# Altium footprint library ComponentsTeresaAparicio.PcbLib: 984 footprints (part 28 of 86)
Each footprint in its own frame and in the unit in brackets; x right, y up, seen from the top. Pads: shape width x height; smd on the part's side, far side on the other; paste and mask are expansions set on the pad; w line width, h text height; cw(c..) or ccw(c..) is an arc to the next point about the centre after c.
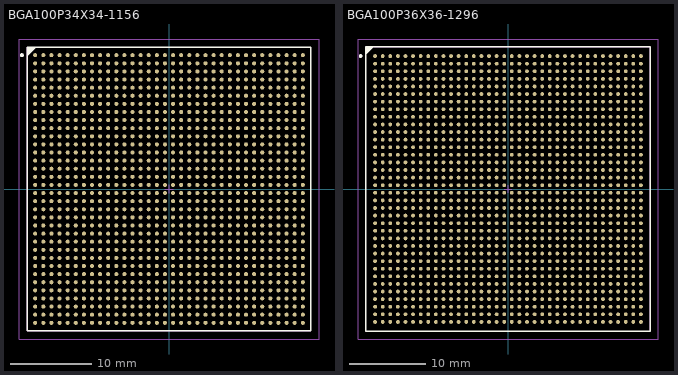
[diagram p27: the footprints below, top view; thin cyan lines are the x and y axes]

## BGA100P34X34-1156 [mm] "BGA, 1156-Leads, Body 35x35mm, Pitch 1mm"
height 3.5
pads (1156):
  round 0.5 smd: A1(-16.5,16.5) A2(-15.5,16.5) A3(-14.5,16.5) A4(-13.5,16.5) A5(-12.5,16.5) A6(-11.5,16.5) A7(-10.5,16.5) A8(-9.5,16.5) A9(-8.5,16.5) A10(-7.5,16.5) A11(-6.5,16.5) A12(-5.5,16.5) A13(-4.5,16.5) A14(-3.5,16.5) A15(-2.5,16.5) A16(-1.5,16.5) A17(-0.5,16.5) A18(0.5,16.5) A19(1.5,16.5) A20(2.5,16.5) A21(3.5,16.5) A22(4.5,16.5) A23(5.5,16.5) A24(6.5,16.5) A25(7.5,16.5) A26(8.5,16.5) A27(9.5,16.5) A28(10.5,16.5) A29(11.5,16.5) A30(12.5,16.5) A31(13.5,16.5) A32(14.5,16.5) A33(15.5,16.5) A34(16.5,16.5) AA1(-16.5,-3.5) AA2(-15.5,-3.5) AA3(-14.5,-3.5) AA4(-13.5,-3.5) AA5(-12.5,-3.5) AA6(-11.5,-3.5) AA7(-10.5,-3.5) AA8(-9.5,-3.5) AA9(-8.5,-3.5) AA10(-7.5,-3.5) AA11(-6.5,-3.5) AA12(-5.5,-3.5) AA13(-4.5,-3.5) AA14(-3.5,-3.5) AA15(-2.5,-3.5) AA16(-1.5,-3.5) AA17(-0.5,-3.5) AA18(0.5,-3.5) AA19(1.5,-3.5) AA20(2.5,-3.5) AA21(3.5,-3.5) AA22(4.5,-3.5) AA23(5.5,-3.5) AA24(6.5,-3.5) AA25(7.5,-3.5) AA26(8.5,-3.5) AA27(9.5,-3.5) AA28(10.5,-3.5) AA29(11.5,-3.5) AA30(12.5,-3.5) AA31(13.5,-3.5) AA32(14.5,-3.5) AA33(15.5,-3.5) AA34(16.5,-3.5) AB1(-16.5,-4.5) AB2(-15.5,-4.5) AB3(-14.5,-4.5) AB4(-13.5,-4.5) AB5(-12.5,-4.5) AB6(-11.5,-4.5) AB7(-10.5,-4.5) AB8(-9.5,-4.5) AB9(-8.5,-4.5) AB10(-7.5,-4.5) AB11(-6.5,-4.5) AB12(-5.5,-4.5) AB13(-4.5,-4.5) AB14(-3.5,-4.5) AB15(-2.5,-4.5) AB16(-1.5,-4.5) AB17(-0.5,-4.5) AB18(0.5,-4.5) AB19(1.5,-4.5) AB20(2.5,-4.5) AB21(3.5,-4.5) AB22(4.5,-4.5) AB23(5.5,-4.5) AB24(6.5,-4.5) AB25(7.5,-4.5) AB26(8.5,-4.5) AB27(9.5,-4.5) AB28(10.5,-4.5) AB29(11.5,-4.5) AB30(12.5,-4.5) AB31(13.5,-4.5) AB32(14.5,-4.5) AB33(15.5,-4.5) AB34(16.5,-4.5) AC1(-16.5,-5.5) AC2(-15.5,-5.5) AC3(-14.5,-5.5) AC4(-13.5,-5.5) AC5(-12.5,-5.5) AC6(-11.5,-5.5) AC7(-10.5,-5.5) AC8(-9.5,-5.5) AC9(-8.5,-5.5) AC10(-7.5,-5.5) AC11(-6.5,-5.5) AC12(-5.5,-5.5) AC13(-4.5,-5.5) AC14(-3.5,-5.5) AC15(-2.5,-5.5) AC16(-1.5,-5.5) AC17(-0.5,-5.5) AC18(0.5,-5.5) AC19(1.5,-5.5) AC20(2.5,-5.5) AC21(3.5,-5.5) AC22(4.5,-5.5) AC23(5.5,-5.5) AC24(6.5,-5.5) AC25(7.5,-5.5) AC26(8.5,-5.5) AC27(9.5,-5.5) AC28(10.5,-5.5) AC29(11.5,-5.5) AC30(12.5,-5.5) AC31(13.5,-5.5) AC32(14.5,-5.5) AC33(15.5,-5.5) AC34(16.5,-5.5) AD1(-16.5,-6.5) AD2(-15.5,-6.5) AD3(-14.5,-6.5) AD4(-13.5,-6.5) AD5(-12.5,-6.5) AD6(-11.5,-6.5) AD7(-10.5,-6.5) AD8(-9.5,-6.5) AD9(-8.5,-6.5) AD10(-7.5,-6.5) AD11(-6.5,-6.5) AD12(-5.5,-6.5) AD13(-4.5,-6.5) AD14(-3.5,-6.5) AD15(-2.5,-6.5) AD16(-1.5,-6.5) AD17(-0.5,-6.5) AD18(0.5,-6.5) AD19(1.5,-6.5) AD20(2.5,-6.5) AD21(3.5,-6.5) AD22(4.5,-6.5) AD23(5.5,-6.5) AD24(6.5,-6.5) AD25(7.5,-6.5) AD26(8.5,-6.5) AD27(9.5,-6.5) AD28(10.5,-6.5) AD29(11.5,-6.5) AD30(12.5,-6.5) AD31(13.5,-6.5) AD32(14.5,-6.5) AD33(15.5,-6.5) AD34(16.5,-6.5) AE1(-16.5,-7.5) AE2(-15.5,-7.5) AE3(-14.5,-7.5) AE4(-13.5,-7.5) AE5(-12.5,-7.5) AE6(-11.5,-7.5) AE7(-10.5,-7.5) AE8(-9.5,-7.5) AE9(-8.5,-7.5) AE10(-7.5,-7.5) AE11(-6.5,-7.5) AE12(-5.5,-7.5) AE13(-4.5,-7.5) AE14(-3.5,-7.5) AE15(-2.5,-7.5) AE16(-1.5,-7.5) AE17(-0.5,-7.5) AE18(0.5,-7.5) AE19(1.5,-7.5) AE20(2.5,-7.5) AE21(3.5,-7.5) AE22(4.5,-7.5) AE23(5.5,-7.5) AE24(6.5,-7.5) AE25(7.5,-7.5) AE26(8.5,-7.5) AE27(9.5,-7.5) AE28(10.5,-7.5) AE29(11.5,-7.5) AE30(12.5,-7.5) AE31(13.5,-7.5) AE32(14.5,-7.5) AE33(15.5,-7.5) AE34(16.5,-7.5) AF1(-16.5,-8.5) AF2(-15.5,-8.5) AF3(-14.5,-8.5) AF4(-13.5,-8.5) AF5(-12.5,-8.5) AF6(-11.5,-8.5) AF7(-10.5,-8.5) AF8(-9.5,-8.5) AF9(-8.5,-8.5) AF10(-7.5,-8.5) AF11(-6.5,-8.5) AF12(-5.5,-8.5) AF13(-4.5,-8.5) AF14(-3.5,-8.5) AF15(-2.5,-8.5) AF16(-1.5,-8.5) AF17(-0.5,-8.5) AF18(0.5,-8.5) AF19(1.5,-8.5) AF20(2.5,-8.5) AF21(3.5,-8.5) AF22(4.5,-8.5) AF23(5.5,-8.5) AF24(6.5,-8.5) AF25(7.5,-8.5) AF26(8.5,-8.5) AF27(9.5,-8.5) AF28(10.5,-8.5) AF29(11.5,-8.5) AF30(12.5,-8.5) AF31(13.5,-8.5) AF32(14.5,-8.5) AF33(15.5,-8.5) AF34(16.5,-8.5) AG1(-16.5,-9.5) AG2(-15.5,-9.5) AG3(-14.5,-9.5) AG4(-13.5,-9.5) AG5(-12.5,-9.5) AG6(-11.5,-9.5) AG7(-10.5,-9.5) AG8(-9.5,-9.5) AG9(-8.5,-9.5) AG10(-7.5,-9.5) AG11(-6.5,-9.5) AG12(-5.5,-9.5) AG13(-4.5,-9.5) AG14(-3.5,-9.5) AG15(-2.5,-9.5) AG16(-1.5,-9.5) AG17(-0.5,-9.5) AG18(0.5,-9.5) AG19(1.5,-9.5) AG20(2.5,-9.5) AG21(3.5,-9.5) AG22(4.5,-9.5) AG23(5.5,-9.5) AG24(6.5,-9.5) AG25(7.5,-9.5) AG26(8.5,-9.5) AG27(9.5,-9.5) AG28(10.5,-9.5) AG29(11.5,-9.5) AG30(12.5,-9.5) AG31(13.5,-9.5) AG32(14.5,-9.5) AG33(15.5,-9.5) AG34(16.5,-9.5) AH1(-16.5,-10.5) AH2(-15.5,-10.5) AH3(-14.5,-10.5) AH4(-13.5,-10.5) AH5(-12.5,-10.5) AH6(-11.5,-10.5) AH7(-10.5,-10.5) AH8(-9.5,-10.5) AH9(-8.5,-10.5) AH10(-7.5,-10.5) AH11(-6.5,-10.5) AH12(-5.5,-10.5) AH13(-4.5,-10.5) AH14(-3.5,-10.5) AH15(-2.5,-10.5) AH16(-1.5,-10.5) AH17(-0.5,-10.5) AH18(0.5,-10.5) AH19(1.5,-10.5) AH20(2.5,-10.5) AH21(3.5,-10.5) AH22(4.5,-10.5) AH23(5.5,-10.5) AH24(6.5,-10.5) AH25(7.5,-10.5) AH26(8.5,-10.5) AH27(9.5,-10.5) AH28(10.5,-10.5) AH29(11.5,-10.5) AH30(12.5,-10.5) AH31(13.5,-10.5) AH32(14.5,-10.5) AH33(15.5,-10.5) AH34(16.5,-10.5) AJ1(-16.5,-11.5) AJ2(-15.5,-11.5) AJ3(-14.5,-11.5) AJ4(-13.5,-11.5) AJ5(-12.5,-11.5) AJ6(-11.5,-11.5) AJ7(-10.5,-11.5) AJ8(-9.5,-11.5) AJ9(-8.5,-11.5) AJ10(-7.5,-11.5) AJ11(-6.5,-11.5) AJ12(-5.5,-11.5) AJ13(-4.5,-11.5) AJ14(-3.5,-11.5) AJ15(-2.5,-11.5) AJ16(-1.5,-11.5) AJ17(-0.5,-11.5) AJ18(0.5,-11.5) AJ19(1.5,-11.5) AJ20(2.5,-11.5) AJ21(3.5,-11.5) AJ22(4.5,-11.5) AJ23(5.5,-11.5) AJ24(6.5,-11.5) AJ25(7.5,-11.5) AJ26(8.5,-11.5) AJ27(9.5,-11.5) AJ28(10.5,-11.5) AJ29(11.5,-11.5) AJ30(12.5,-11.5) AJ31(13.5,-11.5) AJ32(14.5,-11.5) AJ33(15.5,-11.5) AJ34(16.5,-11.5) AK1(-16.5,-12.5) AK2(-15.5,-12.5) AK3(-14.5,-12.5) AK4(-13.5,-12.5) AK5(-12.5,-12.5) AK6(-11.5,-12.5) AK7(-10.5,-12.5) AK8(-9.5,-12.5) AK9(-8.5,-12.5) AK10(-7.5,-12.5) AK11(-6.5,-12.5) AK12(-5.5,-12.5) AK13(-4.5,-12.5) AK14(-3.5,-12.5) AK15(-2.5,-12.5) AK16(-1.5,-12.5) AK17(-0.5,-12.5) AK18(0.5,-12.5) AK19(1.5,-12.5) AK20(2.5,-12.5) AK21(3.5,-12.5) AK22(4.5,-12.5) AK23(5.5,-12.5) AK24(6.5,-12.5) AK25(7.5,-12.5) AK26(8.5,-12.5) AK27(9.5,-12.5) AK28(10.5,-12.5) AK29(11.5,-12.5) AK30(12.5,-12.5) AK31(13.5,-12.5) AK32(14.5,-12.5) AK33(15.5,-12.5) AK34(16.5,-12.5) AL1(-16.5,-13.5) AL2(-15.5,-13.5) AL3(-14.5,-13.5) AL4(-13.5,-13.5) AL5(-12.5,-13.5) AL6(-11.5,-13.5) AL7(-10.5,-13.5) AL8(-9.5,-13.5) AL9(-8.5,-13.5) AL10(-7.5,-13.5) AL11(-6.5,-13.5) AL12(-5.5,-13.5) AL13(-4.5,-13.5) AL14(-3.5,-13.5) AL15(-2.5,-13.5) AL16(-1.5,-13.5) AL17(-0.5,-13.5) AL18(0.5,-13.5) AL19(1.5,-13.5) AL20(2.5,-13.5) AL21(3.5,-13.5) AL22(4.5,-13.5) AL23(5.5,-13.5) AL24(6.5,-13.5) AL25(7.5,-13.5) AL26(8.5,-13.5) AL27(9.5,-13.5) AL28(10.5,-13.5) AL29(11.5,-13.5) AL30(12.5,-13.5) AL31(13.5,-13.5) AL32(14.5,-13.5) AL33(15.5,-13.5) AL34(16.5,-13.5) AM1(-16.5,-14.5) AM2(-15.5,-14.5) AM3(-14.5,-14.5) AM4(-13.5,-14.5) AM5(-12.5,-14.5) AM6(-11.5,-14.5) AM7(-10.5,-14.5) AM8(-9.5,-14.5) AM9(-8.5,-14.5) AM10(-7.5,-14.5) AM11(-6.5,-14.5) AM12(-5.5,-14.5) AM13(-4.5,-14.5) AM14(-3.5,-14.5) AM15(-2.5,-14.5) AM16(-1.5,-14.5) AM17(-0.5,-14.5) AM18(0.5,-14.5) AM19(1.5,-14.5) AM20(2.5,-14.5) AM21(3.5,-14.5) AM22(4.5,-14.5) AM23(5.5,-14.5) AM24(6.5,-14.5) AM25(7.5,-14.5) AM26(8.5,-14.5) AM27(9.5,-14.5) AM28(10.5,-14.5) AM29(11.5,-14.5) AM30(12.5,-14.5) AM31(13.5,-14.5) AM32(14.5,-14.5) AM33(15.5,-14.5) AM34(16.5,-14.5) AN1(-16.5,-15.5) AN2(-15.5,-15.5) AN3(-14.5,-15.5) AN4(-13.5,-15.5) AN5(-12.5,-15.5) AN6(-11.5,-15.5) AN7(-10.5,-15.5) AN8(-9.5,-15.5) AN9(-8.5,-15.5) AN10(-7.5,-15.5) AN11(-6.5,-15.5) AN12(-5.5,-15.5) AN13(-4.5,-15.5) AN14(-3.5,-15.5) AN15(-2.5,-15.5) AN16(-1.5,-15.5) AN17(-0.5,-15.5) AN18(0.5,-15.5) AN19(1.5,-15.5) AN20(2.5,-15.5) AN21(3.5,-15.5) AN22(4.5,-15.5) AN23(5.5,-15.5) AN24(6.5,-15.5) AN25(7.5,-15.5) AN26(8.5,-15.5) AN27(9.5,-15.5) AN28(10.5,-15.5) AN29(11.5,-15.5) AN30(12.5,-15.5) AN31(13.5,-15.5) AN32(14.5,-15.5) AN33(15.5,-15.5) AN34(16.5,-15.5) AP1(-16.5,-16.5) AP2(-15.5,-16.5) AP3(-14.5,-16.5) AP4(-13.5,-16.5) AP5(-12.5,-16.5) AP6(-11.5,-16.5) AP7(-10.5,-16.5) AP8(-9.5,-16.5) AP9(-8.5,-16.5) AP10(-7.5,-16.5) AP11(-6.5,-16.5) AP12(-5.5,-16.5) AP13(-4.5,-16.5) AP14(-3.5,-16.5) AP15(-2.5,-16.5) AP16(-1.5,-16.5) AP17(-0.5,-16.5) AP18(0.5,-16.5) AP19(1.5,-16.5) AP20(2.5,-16.5) AP21(3.5,-16.5) AP22(4.5,-16.5) AP23(5.5,-16.5) AP24(6.5,-16.5) AP25(7.5,-16.5) AP26(8.5,-16.5) AP27(9.5,-16.5) AP28(10.5,-16.5) AP29(11.5,-16.5) AP30(12.5,-16.5) AP31(13.5,-16.5) AP32(14.5,-16.5) AP33(15.5,-16.5) AP34(16.5,-16.5) B1(-16.5,15.5) B2(-15.5,15.5) B3(-14.5,15.5) B4(-13.5,15.5) B5(-12.5,15.5) B6(-11.5,15.5) B7(-10.5,15.5) B8(-9.5,15.5) B9(-8.5,15.5) B10(-7.5,15.5) B11(-6.5,15.5) B12(-5.5,15.5) B13(-4.5,15.5) B14(-3.5,15.5) B15(-2.5,15.5) B16(-1.5,15.5) B17(-0.5,15.5) B18(0.5,15.5) B19(1.5,15.5) B20(2.5,15.5) B21(3.5,15.5) B22(4.5,15.5) B23(5.5,15.5) B24(6.5,15.5) B25(7.5,15.5) B26(8.5,15.5) B27(9.5,15.5) B28(10.5,15.5) B29(11.5,15.5) B30(12.5,15.5) B31(13.5,15.5) B32(14.5,15.5) B33(15.5,15.5) B34(16.5,15.5) C1(-16.5,14.5) C2(-15.5,14.5) C3(-14.5,14.5) C4(-13.5,14.5) C5(-12.5,14.5) C6(-11.5,14.5) C7(-10.5,14.5) C8(-9.5,14.5) C9(-8.5,14.5) C10(-7.5,14.5) C11(-6.5,14.5) C12(-5.5,14.5) C13(-4.5,14.5) C14(-3.5,14.5) C15(-2.5,14.5) C16(-1.5,14.5) C17(-0.5,14.5) C18(0.5,14.5) C19(1.5,14.5) C20(2.5,14.5) C21(3.5,14.5) C22(4.5,14.5) C23(5.5,14.5) C24(6.5,14.5) C25(7.5,14.5) C26(8.5,14.5) C27(9.5,14.5) C28(10.5,14.5) C29(11.5,14.5) C30(12.5,14.5) C31(13.5,14.5) C32(14.5,14.5) C33(15.5,14.5) C34(16.5,14.5) D1(-16.5,13.5) D2(-15.5,13.5) D3(-14.5,13.5) D4(-13.5,13.5) D5(-12.5,13.5) D6(-11.5,13.5) D7(-10.5,13.5) D8(-9.5,13.5) D9(-8.5,13.5) D10(-7.5,13.5) D11(-6.5,13.5) D12(-5.5,13.5) D13(-4.5,13.5) D14(-3.5,13.5) D15(-2.5,13.5) D16(-1.5,13.5) D17(-0.5,13.5) D18(0.5,13.5) D19(1.5,13.5) D20(2.5,13.5) D21(3.5,13.5) D22(4.5,13.5) D23(5.5,13.5) D24(6.5,13.5) D25(7.5,13.5) D26(8.5,13.5) D27(9.5,13.5) D28(10.5,13.5) D29(11.5,13.5) D30(12.5,13.5) D31(13.5,13.5) D32(14.5,13.5) D33(15.5,13.5) D34(16.5,13.5) E1(-16.5,12.5) E2(-15.5,12.5) E3(-14.5,12.5) E4(-13.5,12.5) E5(-12.5,12.5) E6(-11.5,12.5) E7(-10.5,12.5) E8(-9.5,12.5) E9(-8.5,12.5) E10(-7.5,12.5) E11(-6.5,12.5) E12(-5.5,12.5) E13(-4.5,12.5) E14(-3.5,12.5) E15(-2.5,12.5) E16(-1.5,12.5) E17(-0.5,12.5) E18(0.5,12.5) E19(1.5,12.5) E20(2.5,12.5) E21(3.5,12.5) E22(4.5,12.5) E23(5.5,12.5) E24(6.5,12.5) E25(7.5,12.5) E26(8.5,12.5) E27(9.5,12.5) E28(10.5,12.5) E29(11.5,12.5) E30(12.5,12.5) E31(13.5,12.5) E32(14.5,12.5) E33(15.5,12.5) E34(16.5,12.5) F1(-16.5,11.5) F2(-15.5,11.5) F3(-14.5,11.5) F4(-13.5,11.5) F5(-12.5,11.5) F6(-11.5,11.5) F7(-10.5,11.5) F8(-9.5,11.5) F9(-8.5,11.5) F10(-7.5,11.5) F11(-6.5,11.5) F12(-5.5,11.5) F13(-4.5,11.5) F14(-3.5,11.5) F15(-2.5,11.5) F16(-1.5,11.5) F17(-0.5,11.5) F18(0.5,11.5) F19(1.5,11.5) F20(2.5,11.5) F21(3.5,11.5) F22(4.5,11.5) F23(5.5,11.5) F24(6.5,11.5) F25(7.5,11.5) F26(8.5,11.5) F27(9.5,11.5) F28(10.5,11.5) F29(11.5,11.5) F30(12.5,11.5) F31(13.5,11.5) F32(14.5,11.5) F33(15.5,11.5) F34(16.5,11.5) G1(-16.5,10.5) G2(-15.5,10.5) G3(-14.5,10.5) G4(-13.5,10.5) G5(-12.5,10.5) G6(-11.5,10.5) G7(-10.5,10.5) G8(-9.5,10.5) G9(-8.5,10.5) G10(-7.5,10.5) G11(-6.5,10.5) G12(-5.5,10.5) G13(-4.5,10.5) G14(-3.5,10.5) G15(-2.5,10.5) G16(-1.5,10.5) G17(-0.5,10.5) G18(0.5,10.5) G19(1.5,10.5) G20(2.5,10.5) G21(3.5,10.5) G22(4.5,10.5) G23(5.5,10.5) G24(6.5,10.5) G25(7.5,10.5) G26(8.5,10.5) G27(9.5,10.5) G28(10.5,10.5) G29(11.5,10.5) G30(12.5,10.5) G31(13.5,10.5) G32(14.5,10.5) G33(15.5,10.5) G34(16.5,10.5) H1(-16.5,9.5) H2(-15.5,9.5) H3(-14.5,9.5) H4(-13.5,9.5) H5(-12.5,9.5) H6(-11.5,9.5) H7(-10.5,9.5) H8(-9.5,9.5) H9(-8.5,9.5) H10(-7.5,9.5) H11(-6.5,9.5) H12(-5.5,9.5) H13(-4.5,9.5) H14(-3.5,9.5) H15(-2.5,9.5) H16(-1.5,9.5) H17(-0.5,9.5) H18(0.5,9.5) H19(1.5,9.5) H20(2.5,9.5) H21(3.5,9.5) H22(4.5,9.5) H23(5.5,9.5) H24(6.5,9.5) H25(7.5,9.5) H26(8.5,9.5) H27(9.5,9.5) H28(10.5,9.5) H29(11.5,9.5) H30(12.5,9.5) H31(13.5,9.5) H32(14.5,9.5) H33(15.5,9.5) H34(16.5,9.5) J1(-16.5,8.5) J2(-15.5,8.5) J3(-14.5,8.5) J4(-13.5,8.5) J5(-12.5,8.5) J6(-11.5,8.5) J7(-10.5,8.5) J8(-9.5,8.5) J9(-8.5,8.5) J10(-7.5,8.5) J11(-6.5,8.5) J12(-5.5,8.5) J13(-4.5,8.5) J14(-3.5,8.5) J15(-2.5,8.5) J16(-1.5,8.5) J17(-0.5,8.5) J18(0.5,8.5) J19(1.5,8.5) J20(2.5,8.5) J21(3.5,8.5) J22(4.5,8.5) J23(5.5,8.5) J24(6.5,8.5) J25(7.5,8.5) J26(8.5,8.5) J27(9.5,8.5) J28(10.5,8.5) J29(11.5,8.5) J30(12.5,8.5) J31(13.5,8.5) J32(14.5,8.5) J33(15.5,8.5) J34(16.5,8.5) K1(-16.5,7.5) K2(-15.5,7.5) K3(-14.5,7.5) K4(-13.5,7.5) K5(-12.5,7.5) K6(-11.5,7.5) K7(-10.5,7.5) K8(-9.5,7.5) K9(-8.5,7.5) K10(-7.5,7.5) K11(-6.5,7.5) K12(-5.5,7.5) K13(-4.5,7.5) K14(-3.5,7.5) K15(-2.5,7.5) K16(-1.5,7.5) K17(-0.5,7.5) K18(0.5,7.5) K19(1.5,7.5) K20(2.5,7.5) K21(3.5,7.5) K22(4.5,7.5) K23(5.5,7.5) K24(6.5,7.5) K25(7.5,7.5) K26(8.5,7.5) K27(9.5,7.5) K28(10.5,7.5) K29(11.5,7.5) K30(12.5,7.5) K31(13.5,7.5) K32(14.5,7.5) K33(15.5,7.5) K34(16.5,7.5) L1(-16.5,6.5) L2(-15.5,6.5) L3(-14.5,6.5) L4(-13.5,6.5) L5(-12.5,6.5) L6(-11.5,6.5) L7(-10.5,6.5) L8(-9.5,6.5) L9(-8.5,6.5) L10(-7.5,6.5) L11(-6.5,6.5) L12(-5.5,6.5) L13(-4.5,6.5) L14(-3.5,6.5) L15(-2.5,6.5) L16(-1.5,6.5) L17(-0.5,6.5) L18(0.5,6.5) L19(1.5,6.5) L20(2.5,6.5) L21(3.5,6.5) L22(4.5,6.5) L23(5.5,6.5) L24(6.5,6.5) L25(7.5,6.5) L26(8.5,6.5) L27(9.5,6.5) L28(10.5,6.5) L29(11.5,6.5) L30(12.5,6.5) L31(13.5,6.5) L32(14.5,6.5) L33(15.5,6.5) L34(16.5,6.5) M1(-16.5,5.5) M2(-15.5,5.5) M3(-14.5,5.5) M4(-13.5,5.5) M5(-12.5,5.5) M6(-11.5,5.5) M7(-10.5,5.5) M8(-9.5,5.5) M9(-8.5,5.5) M10(-7.5,5.5) M11(-6.5,5.5) M12(-5.5,5.5) M13(-4.5,5.5) M14(-3.5,5.5) M15(-2.5,5.5) M16(-1.5,5.5) M17(-0.5,5.5) M18(0.5,5.5) M19(1.5,5.5) M20(2.5,5.5) M21(3.5,5.5) M22(4.5,5.5) M23(5.5,5.5) M24(6.5,5.5) M25(7.5,5.5) M26(8.5,5.5) M27(9.5,5.5) M28(10.5,5.5) M29(11.5,5.5) M30(12.5,5.5) M31(13.5,5.5) M32(14.5,5.5) M33(15.5,5.5) M34(16.5,5.5) N1(-16.5,4.5) N2(-15.5,4.5) N3(-14.5,4.5) N4(-13.5,4.5) N5(-12.5,4.5) N6(-11.5,4.5) N7(-10.5,4.5) N8(-9.5,4.5) N9(-8.5,4.5) N10(-7.5,4.5) N11(-6.5,4.5) N12(-5.5,4.5) N13(-4.5,4.5) N14(-3.5,4.5) N15(-2.5,4.5) N16(-1.5,4.5) N17(-0.5,4.5) N18(0.5,4.5) N19(1.5,4.5) N20(2.5,4.5) N21(3.5,4.5) N22(4.5,4.5) N23(5.5,4.5) N24(6.5,4.5) N25(7.5,4.5) N26(8.5,4.5) N27(9.5,4.5) N28(10.5,4.5) N29(11.5,4.5) N30(12.5,4.5) N31(13.5,4.5) N32(14.5,4.5) N33(15.5,4.5) N34(16.5,4.5) P1(-16.5,3.5) P2(-15.5,3.5) P3(-14.5,3.5) P4(-13.5,3.5) P5(-12.5,3.5) P6(-11.5,3.5) P7(-10.5,3.5) P8(-9.5,3.5) P9(-8.5,3.5) P10(-7.5,3.5) P11(-6.5,3.5) P12(-5.5,3.5) P13(-4.5,3.5) P14(-3.5,3.5) P15(-2.5,3.5) P16(-1.5,3.5) P17(-0.5,3.5) P18(0.5,3.5) P19(1.5,3.5) P20(2.5,3.5) P21(3.5,3.5) P22(4.5,3.5) P23(5.5,3.5) P24(6.5,3.5) P25(7.5,3.5) P26(8.5,3.5) P27(9.5,3.5) P28(10.5,3.5) P29(11.5,3.5) P30(12.5,3.5) P31(13.5,3.5) P32(14.5,3.5) P33(15.5,3.5) P34(16.5,3.5) R1(-16.5,2.5) R2(-15.5,2.5) R3(-14.5,2.5) R4(-13.5,2.5) R5(-12.5,2.5) R6(-11.5,2.5) R7(-10.5,2.5) R8(-9.5,2.5) R9(-8.5,2.5) R10(-7.5,2.5) R11(-6.5,2.5) R12(-5.5,2.5) R13(-4.5,2.5) R14(-3.5,2.5) R15(-2.5,2.5) R16(-1.5,2.5) R17(-0.5,2.5) R18(0.5,2.5) R19(1.5,2.5) R20(2.5,2.5) R21(3.5,2.5) R22(4.5,2.5) R23(5.5,2.5) R24(6.5,2.5) R25(7.5,2.5) R26(8.5,2.5) R27(9.5,2.5) R28(10.5,2.5) R29(11.5,2.5) R30(12.5,2.5) R31(13.5,2.5) R32(14.5,2.5) R33(15.5,2.5) R34(16.5,2.5) T1(-16.5,1.5) T2(-15.5,1.5) T3(-14.5,1.5) T4(-13.5,1.5) T5(-12.5,1.5) T6(-11.5,1.5) T7(-10.5,1.5) T8(-9.5,1.5) T9(-8.5,1.5) T10(-7.5,1.5) T11(-6.5,1.5) T12(-5.5,1.5) T13(-4.5,1.5) T14(-3.5,1.5) T15(-2.5,1.5) T16(-1.5,1.5) T17(-0.5,1.5) T18(0.5,1.5) T19(1.5,1.5) T20(2.5,1.5) T21(3.5,1.5) T22(4.5,1.5) T23(5.5,1.5) T24(6.5,1.5) T25(7.5,1.5) T26(8.5,1.5) T27(9.5,1.5) T28(10.5,1.5) T29(11.5,1.5) T30(12.5,1.5) T31(13.5,1.5) T32(14.5,1.5) T33(15.5,1.5) T34(16.5,1.5) U1(-16.5,0.5) U2(-15.5,0.5) U3(-14.5,0.5) U4(-13.5,0.5) U5(-12.5,0.5) U6(-11.5,0.5) U7(-10.5,0.5) U8(-9.5,0.5) U9(-8.5,0.5) U10(-7.5,0.5) U11(-6.5,0.5) U12(-5.5,0.5) U13(-4.5,0.5) U14(-3.5,0.5) U15(-2.5,0.5) U16(-1.5,0.5) U17(-0.5,0.5) U18(0.5,0.5) U19(1.5,0.5) U20(2.5,0.5) U21(3.5,0.5) U22(4.5,0.5) U23(5.5,0.5) U24(6.5,0.5) U25(7.5,0.5) U26(8.5,0.5) U27(9.5,0.5) U28(10.5,0.5) U29(11.5,0.5) U30(12.5,0.5) U31(13.5,0.5) U32(14.5,0.5) U33(15.5,0.5) U34(16.5,0.5) V1(-16.5,-0.5) V2(-15.5,-0.5) V3(-14.5,-0.5) V4(-13.5,-0.5) V5(-12.5,-0.5) V6(-11.5,-0.5) V7(-10.5,-0.5) V8(-9.5,-0.5) V9(-8.5,-0.5) V10(-7.5,-0.5) V11(-6.5,-0.5) V12(-5.5,-0.5) V13(-4.5,-0.5) V14(-3.5,-0.5) V15(-2.5,-0.5) V16(-1.5,-0.5) V17(-0.5,-0.5) V18(0.5,-0.5) V19(1.5,-0.5) V20(2.5,-0.5) V21(3.5,-0.5) V22(4.5,-0.5) V23(5.5,-0.5) V24(6.5,-0.5) V25(7.5,-0.5) V26(8.5,-0.5) V27(9.5,-0.5) V28(10.5,-0.5) V29(11.5,-0.5) V30(12.5,-0.5) V31(13.5,-0.5) V32(14.5,-0.5) V33(15.5,-0.5) V34(16.5,-0.5) W1(-16.5,-1.5) W2(-15.5,-1.5) W3(-14.5,-1.5) W4(-13.5,-1.5) W5(-12.5,-1.5) W6(-11.5,-1.5) W7(-10.5,-1.5) W8(-9.5,-1.5) W9(-8.5,-1.5) W10(-7.5,-1.5) W11(-6.5,-1.5) W12(-5.5,-1.5) W13(-4.5,-1.5) W14(-3.5,-1.5) W15(-2.5,-1.5) W16(-1.5,-1.5) W17(-0.5,-1.5) W18(0.5,-1.5) W19(1.5,-1.5) W20(2.5,-1.5) W21(3.5,-1.5) W22(4.5,-1.5) W23(5.5,-1.5) W24(6.5,-1.5) W25(7.5,-1.5) W26(8.5,-1.5) W27(9.5,-1.5) W28(10.5,-1.5) W29(11.5,-1.5) W30(12.5,-1.5) W31(13.5,-1.5) W32(14.5,-1.5) W33(15.5,-1.5) W34(16.5,-1.5) Y1(-16.5,-2.5) Y2(-15.5,-2.5) Y3(-14.5,-2.5) Y4(-13.5,-2.5) Y5(-12.5,-2.5) Y6(-11.5,-2.5) Y7(-10.5,-2.5) Y8(-9.5,-2.5) Y9(-8.5,-2.5) Y10(-7.5,-2.5) Y11(-6.5,-2.5) Y12(-5.5,-2.5) Y13(-4.5,-2.5) Y14(-3.5,-2.5) Y15(-2.5,-2.5) Y16(-1.5,-2.5) Y17(-0.5,-2.5) Y18(0.5,-2.5) Y19(1.5,-2.5) Y20(2.5,-2.5) Y21(3.5,-2.5) Y22(4.5,-2.5) Y23(5.5,-2.5) Y24(6.5,-2.5) Y25(7.5,-2.5) Y26(8.5,-2.5) Y27(9.5,-2.5) Y28(10.5,-2.5) Y29(11.5,-2.5) Y30(12.5,-2.5) Y31(13.5,-2.5) Y32(14.5,-2.5) Y33(15.5,-2.5) Y34(16.5,-2.5)
Top Overlay:
  circle w0.25: c-18.15,16.5 r0.125
  region: -16.5,17.5 -17.5,16.5 -17.5,17.5
  lines w0.2: -17.5,16.5 -16.5,17.5 ; -17.5,-17.5 -17.5,17.5 17.5,17.5 17.5,-17.5 -17.5,-17.5
Mechanical 13:
  lines w0.1: -17.5,-17.5 -17.5,17.5 17.5,17.5 17.5,-17.5 -17.5,-17.5
Mechanical 15:
  lines w0.1: -0.5,0 0.5,0 ; 0,-0.5 0,0.5 ; -18.5,-18.5 -18.5,18.5 18.5,18.5 18.5,-18.5 -18.5,-18.5
3D body: height 0, standoff 0, extent -17.5,-17.5 17.5,17.5

## BGA100P36X36-1296 [mm] "BGA, 1296-Leads, Body 37.5x37.5mm, Pitch 1mm"
height 3.5
pads (1296):
  round 0.5 smd: A1(-17.5,17.5) A2(-16.5,17.5) A3(-15.5,17.5) A4(-14.5,17.5) A5(-13.5,17.5) A6(-12.5,17.5) A7(-11.5,17.5) A8(-10.5,17.5) A9(-9.5,17.5) A10(-8.5,17.5) A11(-7.5,17.5) A12(-6.5,17.5) A13(-5.5,17.5) A14(-4.5,17.5) A15(-3.5,17.5) A16(-2.5,17.5) A17(-1.5,17.5) A18(-0.5,17.5) A19(0.5,17.5) A20(1.5,17.5) A21(2.5,17.5) A22(3.5,17.5) A23(4.5,17.5) A24(5.5,17.5) A25(6.5,17.5) A26(7.5,17.5) A27(8.5,17.5) A28(9.5,17.5) A29(10.5,17.5) A30(11.5,17.5) A31(12.5,17.5) A32(13.5,17.5) A33(14.5,17.5) A34(15.5,17.5) A35(16.5,17.5) A36(17.5,17.5) AA1(-17.5,-2.5) AA2(-16.5,-2.5) AA3(-15.5,-2.5) AA4(-14.5,-2.5) AA5(-13.5,-2.5) AA6(-12.5,-2.5) AA7(-11.5,-2.5) AA8(-10.5,-2.5) AA9(-9.5,-2.5) AA10(-8.5,-2.5) AA11(-7.5,-2.5) AA12(-6.5,-2.5) AA13(-5.5,-2.5) AA14(-4.5,-2.5) AA15(-3.5,-2.5) AA16(-2.5,-2.5) AA17(-1.5,-2.5) AA18(-0.5,-2.5) AA19(0.5,-2.5) AA20(1.5,-2.5) AA21(2.5,-2.5) AA22(3.5,-2.5) AA23(4.5,-2.5) AA24(5.5,-2.5) AA25(6.5,-2.5) AA26(7.5,-2.5) AA27(8.5,-2.5) AA28(9.5,-2.5) AA29(10.5,-2.5) AA30(11.5,-2.5) AA31(12.5,-2.5) AA32(13.5,-2.5) AA33(14.5,-2.5) AA34(15.5,-2.5) AA35(16.5,-2.5) AA36(17.5,-2.5) AB1(-17.5,-3.5) AB2(-16.5,-3.5) AB3(-15.5,-3.5) AB4(-14.5,-3.5) AB5(-13.5,-3.5) AB6(-12.5,-3.5) AB7(-11.5,-3.5) AB8(-10.5,-3.5) AB9(-9.5,-3.5) AB10(-8.5,-3.5) AB11(-7.5,-3.5) AB12(-6.5,-3.5) AB13(-5.5,-3.5) AB14(-4.5,-3.5) AB15(-3.5,-3.5) AB16(-2.5,-3.5) AB17(-1.5,-3.5) AB18(-0.5,-3.5) AB19(0.5,-3.5) AB20(1.5,-3.5) AB21(2.5,-3.5) AB22(3.5,-3.5) AB23(4.5,-3.5) AB24(5.5,-3.5) AB25(6.5,-3.5) AB26(7.5,-3.5) AB27(8.5,-3.5) AB28(9.5,-3.5) AB29(10.5,-3.5) AB30(11.5,-3.5) AB31(12.5,-3.5) AB32(13.5,-3.5) AB33(14.5,-3.5) AB34(15.5,-3.5) AB35(16.5,-3.5) AB36(17.5,-3.5) AC1(-17.5,-4.5) AC2(-16.5,-4.5) AC3(-15.5,-4.5) AC4(-14.5,-4.5) AC5(-13.5,-4.5) AC6(-12.5,-4.5) AC7(-11.5,-4.5) AC8(-10.5,-4.5) AC9(-9.5,-4.5) AC10(-8.5,-4.5) AC11(-7.5,-4.5) AC12(-6.5,-4.5) AC13(-5.5,-4.5) AC14(-4.5,-4.5) AC15(-3.5,-4.5) AC16(-2.5,-4.5) AC17(-1.5,-4.5) AC18(-0.5,-4.5) AC19(0.5,-4.5) AC20(1.5,-4.5) AC21(2.5,-4.5) AC22(3.5,-4.5) AC23(4.5,-4.5) AC24(5.5,-4.5) AC25(6.5,-4.5) AC26(7.5,-4.5) AC27(8.5,-4.5) AC28(9.5,-4.5) AC29(10.5,-4.5) AC30(11.5,-4.5) AC31(12.5,-4.5) AC32(13.5,-4.5) AC33(14.5,-4.5) AC34(15.5,-4.5) AC35(16.5,-4.5) AC36(17.5,-4.5) AD1(-17.5,-5.5) AD2(-16.5,-5.5) AD3(-15.5,-5.5) AD4(-14.5,-5.5) AD5(-13.5,-5.5) AD6(-12.5,-5.5) AD7(-11.5,-5.5) AD8(-10.5,-5.5) AD9(-9.5,-5.5) AD10(-8.5,-5.5) AD11(-7.5,-5.5) AD12(-6.5,-5.5) AD13(-5.5,-5.5) AD14(-4.5,-5.5) AD15(-3.5,-5.5) AD16(-2.5,-5.5) AD17(-1.5,-5.5) AD18(-0.5,-5.5) AD19(0.5,-5.5) AD20(1.5,-5.5) AD21(2.5,-5.5) AD22(3.5,-5.5) AD23(4.5,-5.5) AD24(5.5,-5.5) AD25(6.5,-5.5) AD26(7.5,-5.5) AD27(8.5,-5.5) AD28(9.5,-5.5) AD29(10.5,-5.5) AD30(11.5,-5.5) AD31(12.5,-5.5) AD32(13.5,-5.5) AD33(14.5,-5.5) AD34(15.5,-5.5) AD35(16.5,-5.5) AD36(17.5,-5.5) AE1(-17.5,-6.5) AE2(-16.5,-6.5) AE3(-15.5,-6.5) AE4(-14.5,-6.5) AE5(-13.5,-6.5) AE6(-12.5,-6.5) AE7(-11.5,-6.5) AE8(-10.5,-6.5) AE9(-9.5,-6.5) AE10(-8.5,-6.5) AE11(-7.5,-6.5) AE12(-6.5,-6.5) AE13(-5.5,-6.5) AE14(-4.5,-6.5) AE15(-3.5,-6.5) AE16(-2.5,-6.5) AE17(-1.5,-6.5) AE18(-0.5,-6.5) AE19(0.5,-6.5) AE20(1.5,-6.5) AE21(2.5,-6.5) AE22(3.5,-6.5) AE23(4.5,-6.5) AE24(5.5,-6.5) AE25(6.5,-6.5) AE26(7.5,-6.5) AE27(8.5,-6.5) AE28(9.5,-6.5) AE29(10.5,-6.5) AE30(11.5,-6.5) AE31(12.5,-6.5) AE32(13.5,-6.5) AE33(14.5,-6.5) AE34(15.5,-6.5) AE35(16.5,-6.5) AE36(17.5,-6.5) AF1(-17.5,-7.5) AF2(-16.5,-7.5) AF3(-15.5,-7.5) AF4(-14.5,-7.5) AF5(-13.5,-7.5) AF6(-12.5,-7.5) AF7(-11.5,-7.5) AF8(-10.5,-7.5) AF9(-9.5,-7.5) AF10(-8.5,-7.5) AF11(-7.5,-7.5) AF12(-6.5,-7.5) AF13(-5.5,-7.5) AF14(-4.5,-7.5) AF15(-3.5,-7.5) AF16(-2.5,-7.5) AF17(-1.5,-7.5) AF18(-0.5,-7.5) AF19(0.5,-7.5) AF20(1.5,-7.5) AF21(2.5,-7.5) AF22(3.5,-7.5) AF23(4.5,-7.5) AF24(5.5,-7.5) AF25(6.5,-7.5) AF26(7.5,-7.5) AF27(8.5,-7.5) AF28(9.5,-7.5) AF29(10.5,-7.5) AF30(11.5,-7.5) AF31(12.5,-7.5) AF32(13.5,-7.5) AF33(14.5,-7.5) AF34(15.5,-7.5) AF35(16.5,-7.5) AF36(17.5,-7.5) AG1(-17.5,-8.5) AG2(-16.5,-8.5) AG3(-15.5,-8.5) AG4(-14.5,-8.5) AG5(-13.5,-8.5) AG6(-12.5,-8.5) AG7(-11.5,-8.5) AG8(-10.5,-8.5) AG9(-9.5,-8.5) AG10(-8.5,-8.5) AG11(-7.5,-8.5) AG12(-6.5,-8.5) AG13(-5.5,-8.5) AG14(-4.5,-8.5) AG15(-3.5,-8.5) AG16(-2.5,-8.5) AG17(-1.5,-8.5) AG18(-0.5,-8.5) AG19(0.5,-8.5) AG20(1.5,-8.5) AG21(2.5,-8.5) AG22(3.5,-8.5) AG23(4.5,-8.5) AG24(5.5,-8.5) AG25(6.5,-8.5) AG26(7.5,-8.5) AG27(8.5,-8.5) AG28(9.5,-8.5) AG29(10.5,-8.5) AG30(11.5,-8.5) AG31(12.5,-8.5) AG32(13.5,-8.5) AG33(14.5,-8.5) AG34(15.5,-8.5) AG35(16.5,-8.5) AG36(17.5,-8.5) AH1(-17.5,-9.5) AH2(-16.5,-9.5) AH3(-15.5,-9.5) AH4(-14.5,-9.5) AH5(-13.5,-9.5) AH6(-12.5,-9.5) AH7(-11.5,-9.5) AH8(-10.5,-9.5) AH9(-9.5,-9.5) AH10(-8.5,-9.5) AH11(-7.5,-9.5) AH12(-6.5,-9.5) AH13(-5.5,-9.5) AH14(-4.5,-9.5) AH15(-3.5,-9.5) AH16(-2.5,-9.5) AH17(-1.5,-9.5) AH18(-0.5,-9.5) AH19(0.5,-9.5) AH20(1.5,-9.5) AH21(2.5,-9.5) AH22(3.5,-9.5) AH23(4.5,-9.5) AH24(5.5,-9.5) AH25(6.5,-9.5) AH26(7.5,-9.5) AH27(8.5,-9.5) AH28(9.5,-9.5) AH29(10.5,-9.5) AH30(11.5,-9.5) AH31(12.5,-9.5) AH32(13.5,-9.5) AH33(14.5,-9.5) AH34(15.5,-9.5) AH35(16.5,-9.5) AH36(17.5,-9.5) AJ1(-17.5,-10.5) AJ2(-16.5,-10.5) AJ3(-15.5,-10.5) AJ4(-14.5,-10.5) AJ5(-13.5,-10.5) AJ6(-12.5,-10.5) AJ7(-11.5,-10.5) AJ8(-10.5,-10.5) AJ9(-9.5,-10.5) AJ10(-8.5,-10.5) AJ11(-7.5,-10.5) AJ12(-6.5,-10.5) AJ13(-5.5,-10.5) AJ14(-4.5,-10.5) AJ15(-3.5,-10.5) AJ16(-2.5,-10.5) AJ17(-1.5,-10.5) AJ18(-0.5,-10.5) AJ19(0.5,-10.5) AJ20(1.5,-10.5) AJ21(2.5,-10.5) AJ22(3.5,-10.5) AJ23(4.5,-10.5) AJ24(5.5,-10.5) AJ25(6.5,-10.5) AJ26(7.5,-10.5) AJ27(8.5,-10.5) AJ28(9.5,-10.5) AJ29(10.5,-10.5) AJ30(11.5,-10.5) AJ31(12.5,-10.5) AJ32(13.5,-10.5) AJ33(14.5,-10.5) AJ34(15.5,-10.5) AJ35(16.5,-10.5) AJ36(17.5,-10.5) AK1(-17.5,-11.5) AK2(-16.5,-11.5) AK3(-15.5,-11.5) AK4(-14.5,-11.5) AK5(-13.5,-11.5) AK6(-12.5,-11.5) AK7(-11.5,-11.5) AK8(-10.5,-11.5) AK9(-9.5,-11.5) AK10(-8.5,-11.5) AK11(-7.5,-11.5) AK12(-6.5,-11.5) AK13(-5.5,-11.5) AK14(-4.5,-11.5) AK15(-3.5,-11.5) AK16(-2.5,-11.5) AK17(-1.5,-11.5) AK18(-0.5,-11.5) AK19(0.5,-11.5) AK20(1.5,-11.5) AK21(2.5,-11.5) AK22(3.5,-11.5) AK23(4.5,-11.5) AK24(5.5,-11.5) AK25(6.5,-11.5) AK26(7.5,-11.5) AK27(8.5,-11.5) AK28(9.5,-11.5) AK29(10.5,-11.5) AK30(11.5,-11.5) AK31(12.5,-11.5) AK32(13.5,-11.5) AK33(14.5,-11.5) AK34(15.5,-11.5) AK35(16.5,-11.5) AK36(17.5,-11.5) AL1(-17.5,-12.5) AL2(-16.5,-12.5) AL3(-15.5,-12.5) AL4(-14.5,-12.5) AL5(-13.5,-12.5) AL6(-12.5,-12.5) AL7(-11.5,-12.5) AL8(-10.5,-12.5) AL9(-9.5,-12.5) AL10(-8.5,-12.5) AL11(-7.5,-12.5) AL12(-6.5,-12.5) AL13(-5.5,-12.5) AL14(-4.5,-12.5) AL15(-3.5,-12.5) AL16(-2.5,-12.5) AL17(-1.5,-12.5) AL18(-0.5,-12.5) AL19(0.5,-12.5) AL20(1.5,-12.5) AL21(2.5,-12.5) AL22(3.5,-12.5) AL23(4.5,-12.5) AL24(5.5,-12.5) AL25(6.5,-12.5) AL26(7.5,-12.5) AL27(8.5,-12.5) AL28(9.5,-12.5) AL29(10.5,-12.5) AL30(11.5,-12.5) AL31(12.5,-12.5) AL32(13.5,-12.5) AL33(14.5,-12.5) AL34(15.5,-12.5) AL35(16.5,-12.5) AL36(17.5,-12.5) AM1(-17.5,-13.5) AM2(-16.5,-13.5) AM3(-15.5,-13.5) AM4(-14.5,-13.5) AM5(-13.5,-13.5) AM6(-12.5,-13.5) AM7(-11.5,-13.5) AM8(-10.5,-13.5) AM9(-9.5,-13.5) AM10(-8.5,-13.5) AM11(-7.5,-13.5) AM12(-6.5,-13.5) AM13(-5.5,-13.5) AM14(-4.5,-13.5) AM15(-3.5,-13.5) AM16(-2.5,-13.5) AM17(-1.5,-13.5) AM18(-0.5,-13.5) AM19(0.5,-13.5) AM20(1.5,-13.5) AM21(2.5,-13.5) AM22(3.5,-13.5) AM23(4.5,-13.5) AM24(5.5,-13.5) AM25(6.5,-13.5) AM26(7.5,-13.5) AM27(8.5,-13.5) AM28(9.5,-13.5) AM29(10.5,-13.5) AM30(11.5,-13.5) AM31(12.5,-13.5) AM32(13.5,-13.5) AM33(14.5,-13.5) AM34(15.5,-13.5) AM35(16.5,-13.5) AM36(17.5,-13.5) AN1(-17.5,-14.5) AN2(-16.5,-14.5) AN3(-15.5,-14.5) AN4(-14.5,-14.5) AN5(-13.5,-14.5) AN6(-12.5,-14.5) AN7(-11.5,-14.5) AN8(-10.5,-14.5) AN9(-9.5,-14.5) AN10(-8.5,-14.5) AN11(-7.5,-14.5) AN12(-6.5,-14.5) AN13(-5.5,-14.5) AN14(-4.5,-14.5) AN15(-3.5,-14.5) AN16(-2.5,-14.5) AN17(-1.5,-14.5) AN18(-0.5,-14.5) AN19(0.5,-14.5) AN20(1.5,-14.5) AN21(2.5,-14.5) AN22(3.5,-14.5) AN23(4.5,-14.5) AN24(5.5,-14.5) AN25(6.5,-14.5) AN26(7.5,-14.5) AN27(8.5,-14.5) AN28(9.5,-14.5) AN29(10.5,-14.5) AN30(11.5,-14.5) AN31(12.5,-14.5) AN32(13.5,-14.5) AN33(14.5,-14.5) AN34(15.5,-14.5) AN35(16.5,-14.5) AN36(17.5,-14.5) AP1(-17.5,-15.5) AP2(-16.5,-15.5) AP3(-15.5,-15.5) AP4(-14.5,-15.5) AP5(-13.5,-15.5) AP6(-12.5,-15.5) AP7(-11.5,-15.5) AP8(-10.5,-15.5) AP9(-9.5,-15.5) AP10(-8.5,-15.5) AP11(-7.5,-15.5) AP12(-6.5,-15.5) AP13(-5.5,-15.5) AP14(-4.5,-15.5) AP15(-3.5,-15.5) AP16(-2.5,-15.5) AP17(-1.5,-15.5) AP18(-0.5,-15.5) AP19(0.5,-15.5) AP20(1.5,-15.5) AP21(2.5,-15.5) AP22(3.5,-15.5) AP23(4.5,-15.5) AP24(5.5,-15.5) AP25(6.5,-15.5) AP26(7.5,-15.5) AP27(8.5,-15.5) AP28(9.5,-15.5) AP29(10.5,-15.5) AP30(11.5,-15.5) AP31(12.5,-15.5) AP32(13.5,-15.5) AP33(14.5,-15.5) AP34(15.5,-15.5) AP35(16.5,-15.5) AP36(17.5,-15.5) AR1(-17.5,-16.5) AR2(-16.5,-16.5) AR3(-15.5,-16.5) AR4(-14.5,-16.5) AR5(-13.5,-16.5) AR6(-12.5,-16.5) AR7(-11.5,-16.5) AR8(-10.5,-16.5) AR9(-9.5,-16.5) AR10(-8.5,-16.5) AR11(-7.5,-16.5) AR12(-6.5,-16.5) AR13(-5.5,-16.5) AR14(-4.5,-16.5) AR15(-3.5,-16.5) AR16(-2.5,-16.5) AR17(-1.5,-16.5) AR18(-0.5,-16.5) AR19(0.5,-16.5) AR20(1.5,-16.5) AR21(2.5,-16.5) AR22(3.5,-16.5) AR23(4.5,-16.5) AR24(5.5,-16.5) AR25(6.5,-16.5) AR26(7.5,-16.5) AR27(8.5,-16.5) AR28(9.5,-16.5) AR29(10.5,-16.5) AR30(11.5,-16.5) AR31(12.5,-16.5) AR32(13.5,-16.5) AR33(14.5,-16.5) AR34(15.5,-16.5) AR35(16.5,-16.5) AR36(17.5,-16.5) AT1(-17.5,-17.5) AT2(-16.5,-17.5) AT3(-15.5,-17.5) AT4(-14.5,-17.5) AT5(-13.5,-17.5) AT6(-12.5,-17.5) AT7(-11.5,-17.5) AT8(-10.5,-17.5) AT9(-9.5,-17.5) AT10(-8.5,-17.5) AT11(-7.5,-17.5) AT12(-6.5,-17.5) AT13(-5.5,-17.5) AT14(-4.5,-17.5) AT15(-3.5,-17.5) AT16(-2.5,-17.5) AT17(-1.5,-17.5) AT18(-0.5,-17.5) AT19(0.5,-17.5) AT20(1.5,-17.5) AT21(2.5,-17.5) AT22(3.5,-17.5) AT23(4.5,-17.5) AT24(5.5,-17.5) AT25(6.5,-17.5) AT26(7.5,-17.5) AT27(8.5,-17.5) AT28(9.5,-17.5) AT29(10.5,-17.5) AT30(11.5,-17.5) AT31(12.5,-17.5) AT32(13.5,-17.5) AT33(14.5,-17.5) AT34(15.5,-17.5) AT35(16.5,-17.5) AT36(17.5,-17.5) B1(-17.5,16.5) B2(-16.5,16.5) B3(-15.5,16.5) B4(-14.5,16.5) B5(-13.5,16.5) B6(-12.5,16.5) B7(-11.5,16.5) B8(-10.5,16.5) B9(-9.5,16.5) B10(-8.5,16.5) B11(-7.5,16.5) B12(-6.5,16.5) B13(-5.5,16.5) B14(-4.5,16.5) B15(-3.5,16.5) B16(-2.5,16.5) B17(-1.5,16.5) B18(-0.5,16.5) B19(0.5,16.5) B20(1.5,16.5) B21(2.5,16.5) B22(3.5,16.5) B23(4.5,16.5) B24(5.5,16.5) B25(6.5,16.5) B26(7.5,16.5) B27(8.5,16.5) B28(9.5,16.5) B29(10.5,16.5) B30(11.5,16.5) B31(12.5,16.5) B32(13.5,16.5) B33(14.5,16.5) B34(15.5,16.5) B35(16.5,16.5) B36(17.5,16.5) C1(-17.5,15.5) C2(-16.5,15.5) C3(-15.5,15.5) C4(-14.5,15.5) C5(-13.5,15.5) C6(-12.5,15.5) C7(-11.5,15.5) C8(-10.5,15.5) C9(-9.5,15.5) C10(-8.5,15.5) C11(-7.5,15.5) C12(-6.5,15.5) C13(-5.5,15.5) C14(-4.5,15.5) C15(-3.5,15.5) C16(-2.5,15.5) C17(-1.5,15.5) C18(-0.5,15.5) C19(0.5,15.5) C20(1.5,15.5) C21(2.5,15.5) C22(3.5,15.5) C23(4.5,15.5) C24(5.5,15.5) C25(6.5,15.5) C26(7.5,15.5) C27(8.5,15.5) C28(9.5,15.5) C29(10.5,15.5) C30(11.5,15.5) C31(12.5,15.5) C32(13.5,15.5) C33(14.5,15.5) C34(15.5,15.5) C35(16.5,15.5) C36(17.5,15.5) D1(-17.5,14.5) D2(-16.5,14.5) D3(-15.5,14.5) D4(-14.5,14.5) D5(-13.5,14.5) D6(-12.5,14.5) D7(-11.5,14.5) D8(-10.5,14.5) D9(-9.5,14.5) D10(-8.5,14.5) D11(-7.5,14.5) D12(-6.5,14.5) D13(-5.5,14.5) D14(-4.5,14.5) D15(-3.5,14.5) D16(-2.5,14.5) D17(-1.5,14.5) D18(-0.5,14.5) D19(0.5,14.5) D20(1.5,14.5) D21(2.5,14.5) D22(3.5,14.5) D23(4.5,14.5) D24(5.5,14.5) D25(6.5,14.5) D26(7.5,14.5) D27(8.5,14.5) D28(9.5,14.5) D29(10.5,14.5) D30(11.5,14.5) D31(12.5,14.5) D32(13.5,14.5) D33(14.5,14.5) D34(15.5,14.5) D35(16.5,14.5) D36(17.5,14.5) E1(-17.5,13.5) E2(-16.5,13.5) E3(-15.5,13.5) E4(-14.5,13.5) E5(-13.5,13.5) E6(-12.5,13.5) E7(-11.5,13.5) E8(-10.5,13.5) E9(-9.5,13.5) E10(-8.5,13.5) E11(-7.5,13.5) E12(-6.5,13.5) E13(-5.5,13.5) E14(-4.5,13.5) E15(-3.5,13.5) E16(-2.5,13.5) E17(-1.5,13.5) E18(-0.5,13.5) E19(0.5,13.5) E20(1.5,13.5) E21(2.5,13.5) E22(3.5,13.5) E23(4.5,13.5) E24(5.5,13.5) E25(6.5,13.5) E26(7.5,13.5) E27(8.5,13.5) E28(9.5,13.5) E29(10.5,13.5) E30(11.5,13.5) E31(12.5,13.5) E32(13.5,13.5) E33(14.5,13.5) E34(15.5,13.5) E35(16.5,13.5) E36(17.5,13.5) F1(-17.5,12.5) F2(-16.5,12.5) F3(-15.5,12.5) F4(-14.5,12.5) F5(-13.5,12.5) F6(-12.5,12.5) F7(-11.5,12.5) F8(-10.5,12.5) F9(-9.5,12.5) F10(-8.5,12.5) F11(-7.5,12.5) F12(-6.5,12.5) F13(-5.5,12.5) F14(-4.5,12.5) F15(-3.5,12.5) F16(-2.5,12.5) F17(-1.5,12.5) F18(-0.5,12.5) F19(0.5,12.5) F20(1.5,12.5) F21(2.5,12.5) F22(3.5,12.5) F23(4.5,12.5) F24(5.5,12.5) F25(6.5,12.5) F26(7.5,12.5) F27(8.5,12.5) F28(9.5,12.5) F29(10.5,12.5) F30(11.5,12.5) F31(12.5,12.5) F32(13.5,12.5) F33(14.5,12.5) F34(15.5,12.5) F35(16.5,12.5) F36(17.5,12.5) G1(-17.5,11.5) G2(-16.5,11.5) G3(-15.5,11.5) G4(-14.5,11.5) G5(-13.5,11.5) G6(-12.5,11.5) G7(-11.5,11.5) G8(-10.5,11.5) G9(-9.5,11.5) G10(-8.5,11.5) G11(-7.5,11.5) G12(-6.5,11.5) G13(-5.5,11.5) G14(-4.5,11.5) G15(-3.5,11.5) G16(-2.5,11.5) G17(-1.5,11.5) G18(-0.5,11.5) G19(0.5,11.5) G20(1.5,11.5) G21(2.5,11.5) G22(3.5,11.5) G23(4.5,11.5) G24(5.5,11.5) G25(6.5,11.5) G26(7.5,11.5) G27(8.5,11.5) G28(9.5,11.5) G29(10.5,11.5) G30(11.5,11.5) G31(12.5,11.5) G32(13.5,11.5) G33(14.5,11.5) G34(15.5,11.5) G35(16.5,11.5) G36(17.5,11.5) H1(-17.5,10.5) H2(-16.5,10.5) H3(-15.5,10.5) H4(-14.5,10.5) H5(-13.5,10.5) H6(-12.5,10.5) H7(-11.5,10.5) H8(-10.5,10.5) H9(-9.5,10.5) H10(-8.5,10.5) H11(-7.5,10.5) H12(-6.5,10.5) H13(-5.5,10.5) H14(-4.5,10.5) H15(-3.5,10.5) H16(-2.5,10.5) H17(-1.5,10.5) H18(-0.5,10.5) H19(0.5,10.5) H20(1.5,10.5) H21(2.5,10.5) H22(3.5,10.5) H23(4.5,10.5) H24(5.5,10.5) H25(6.5,10.5) H26(7.5,10.5) H27(8.5,10.5) H28(9.5,10.5) H29(10.5,10.5) H30(11.5,10.5) H31(12.5,10.5) H32(13.5,10.5) H33(14.5,10.5) H34(15.5,10.5) H35(16.5,10.5) H36(17.5,10.5) J1(-17.5,9.5) J2(-16.5,9.5) J3(-15.5,9.5) J4(-14.5,9.5) J5(-13.5,9.5) J6(-12.5,9.5) J7(-11.5,9.5) J8(-10.5,9.5) J9(-9.5,9.5) J10(-8.5,9.5) J11(-7.5,9.5) J12(-6.5,9.5) J13(-5.5,9.5) J14(-4.5,9.5) J15(-3.5,9.5) J16(-2.5,9.5) J17(-1.5,9.5) J18(-0.5,9.5) J19(0.5,9.5) J20(1.5,9.5) J21(2.5,9.5) J22(3.5,9.5) J23(4.5,9.5) J24(5.5,9.5) J25(6.5,9.5) J26(7.5,9.5) J27(8.5,9.5) J28(9.5,9.5) J29(10.5,9.5) J30(11.5,9.5) J31(12.5,9.5) J32(13.5,9.5) J33(14.5,9.5) J34(15.5,9.5) J35(16.5,9.5) J36(17.5,9.5) K1(-17.5,8.5) K2(-16.5,8.5) K3(-15.5,8.5) K4(-14.5,8.5) K5(-13.5,8.5) K6(-12.5,8.5) K7(-11.5,8.5) K8(-10.5,8.5) K9(-9.5,8.5) K10(-8.5,8.5) K11(-7.5,8.5) K12(-6.5,8.5) K13(-5.5,8.5) K14(-4.5,8.5) K15(-3.5,8.5) K16(-2.5,8.5) K17(-1.5,8.5) K18(-0.5,8.5) K19(0.5,8.5) K20(1.5,8.5) K21(2.5,8.5) K22(3.5,8.5) K23(4.5,8.5) K24(5.5,8.5) K25(6.5,8.5) K26(7.5,8.5) K27(8.5,8.5) K28(9.5,8.5) K29(10.5,8.5) K30(11.5,8.5) K31(12.5,8.5) K32(13.5,8.5) K33(14.5,8.5) K34(15.5,8.5) K35(16.5,8.5) K36(17.5,8.5) L1(-17.5,7.5) L2(-16.5,7.5) L3(-15.5,7.5) L4(-14.5,7.5) L5(-13.5,7.5) L6(-12.5,7.5) L7(-11.5,7.5) L8(-10.5,7.5) L9(-9.5,7.5) L10(-8.5,7.5) L11(-7.5,7.5) L12(-6.5,7.5) L13(-5.5,7.5) L14(-4.5,7.5) L15(-3.5,7.5) L16(-2.5,7.5) L17(-1.5,7.5) L18(-0.5,7.5) L19(0.5,7.5) L20(1.5,7.5) L21(2.5,7.5) L22(3.5,7.5) L23(4.5,7.5) L24(5.5,7.5) L25(6.5,7.5) L26(7.5,7.5) L27(8.5,7.5) L28(9.5,7.5) L29(10.5,7.5) L30(11.5,7.5) L31(12.5,7.5) L32(13.5,7.5) L33(14.5,7.5) L34(15.5,7.5) L35(16.5,7.5) L36(17.5,7.5) M1(-17.5,6.5) M2(-16.5,6.5) M3(-15.5,6.5) M4(-14.5,6.5) M5(-13.5,6.5) M6(-12.5,6.5) M7(-11.5,6.5) M8(-10.5,6.5) M9(-9.5,6.5) M10(-8.5,6.5) M11(-7.5,6.5) M12(-6.5,6.5) M13(-5.5,6.5) M14(-4.5,6.5) M15(-3.5,6.5) M16(-2.5,6.5) M17(-1.5,6.5) M18(-0.5,6.5) M19(0.5,6.5) M20(1.5,6.5) M21(2.5,6.5) M22(3.5,6.5) M23(4.5,6.5) M24(5.5,6.5) M25(6.5,6.5) M26(7.5,6.5) M27(8.5,6.5) M28(9.5,6.5) M29(10.5,6.5) M30(11.5,6.5) M31(12.5,6.5) M32(13.5,6.5) M33(14.5,6.5) M34(15.5,6.5) M35(16.5,6.5) M36(17.5,6.5) N1(-17.5,5.5) N2(-16.5,5.5) N3(-15.5,5.5) N4(-14.5,5.5) N5(-13.5,5.5) N6(-12.5,5.5) N7(-11.5,5.5) N8(-10.5,5.5) N9(-9.5,5.5) N10(-8.5,5.5) N11(-7.5,5.5) N12(-6.5,5.5) N13(-5.5,5.5) N14(-4.5,5.5) N15(-3.5,5.5) N16(-2.5,5.5) N17(-1.5,5.5) N18(-0.5,5.5) N19(0.5,5.5) N20(1.5,5.5) N21(2.5,5.5) N22(3.5,5.5) N23(4.5,5.5) N24(5.5,5.5) N25(6.5,5.5) N26(7.5,5.5) N27(8.5,5.5) N28(9.5,5.5) N29(10.5,5.5) N30(11.5,5.5) N31(12.5,5.5) N32(13.5,5.5) N33(14.5,5.5) N34(15.5,5.5) N35(16.5,5.5) N36(17.5,5.5) P1(-17.5,4.5) P2(-16.5,4.5) P3(-15.5,4.5) P4(-14.5,4.5) P5(-13.5,4.5) P6(-12.5,4.5) P7(-11.5,4.5) P8(-10.5,4.5) P9(-9.5,4.5) P10(-8.5,4.5) P11(-7.5,4.5) P12(-6.5,4.5) P13(-5.5,4.5) P14(-4.5,4.5) P15(-3.5,4.5) P16(-2.5,4.5) P17(-1.5,4.5) P18(-0.5,4.5) P19(0.5,4.5) P20(1.5,4.5) P21(2.5,4.5) P22(3.5,4.5) P23(4.5,4.5) P24(5.5,4.5) P25(6.5,4.5) P26(7.5,4.5) P27(8.5,4.5) P28(9.5,4.5) P29(10.5,4.5) P30(11.5,4.5) P31(12.5,4.5) P32(13.5,4.5) P33(14.5,4.5) P34(15.5,4.5) P35(16.5,4.5) P36(17.5,4.5) R1(-17.5,3.5) R2(-16.5,3.5) R3(-15.5,3.5) R4(-14.5,3.5) R5(-13.5,3.5) R6(-12.5,3.5) R7(-11.5,3.5) R8(-10.5,3.5) R9(-9.5,3.5) R10(-8.5,3.5) R11(-7.5,3.5) R12(-6.5,3.5) R13(-5.5,3.5) R14(-4.5,3.5) R15(-3.5,3.5) R16(-2.5,3.5) R17(-1.5,3.5) R18(-0.5,3.5) R19(0.5,3.5) R20(1.5,3.5) R21(2.5,3.5) R22(3.5,3.5) R23(4.5,3.5) R24(5.5,3.5) R25(6.5,3.5) R26(7.5,3.5) R27(8.5,3.5) R28(9.5,3.5) R29(10.5,3.5) R30(11.5,3.5) R31(12.5,3.5) R32(13.5,3.5) R33(14.5,3.5) R34(15.5,3.5) R35(16.5,3.5) R36(17.5,3.5) T1(-17.5,2.5) T2(-16.5,2.5) T3(-15.5,2.5) T4(-14.5,2.5) T5(-13.5,2.5) T6(-12.5,2.5) T7(-11.5,2.5) T8(-10.5,2.5) T9(-9.5,2.5) T10(-8.5,2.5) T11(-7.5,2.5) T12(-6.5,2.5) T13(-5.5,2.5) T14(-4.5,2.5) T15(-3.5,2.5) T16(-2.5,2.5) T17(-1.5,2.5) T18(-0.5,2.5) T19(0.5,2.5) T20(1.5,2.5) T21(2.5,2.5) T22(3.5,2.5) T23(4.5,2.5) T24(5.5,2.5) T25(6.5,2.5) T26(7.5,2.5) T27(8.5,2.5) T28(9.5,2.5) T29(10.5,2.5) T30(11.5,2.5) T31(12.5,2.5) T32(13.5,2.5) T33(14.5,2.5) T34(15.5,2.5) T35(16.5,2.5) T36(17.5,2.5) U1(-17.5,1.5) U2(-16.5,1.5) U3(-15.5,1.5) U4(-14.5,1.5) U5(-13.5,1.5) U6(-12.5,1.5) U7(-11.5,1.5) U8(-10.5,1.5) U9(-9.5,1.5) U10(-8.5,1.5) U11(-7.5,1.5) U12(-6.5,1.5) U13(-5.5,1.5) U14(-4.5,1.5) U15(-3.5,1.5) U16(-2.5,1.5) U17(-1.5,1.5) U18(-0.5,1.5) U19(0.5,1.5) U20(1.5,1.5) U21(2.5,1.5) U22(3.5,1.5) U23(4.5,1.5) U24(5.5,1.5) U25(6.5,1.5) U26(7.5,1.5) U27(8.5,1.5) U28(9.5,1.5) U29(10.5,1.5) U30(11.5,1.5) U31(12.5,1.5) U32(13.5,1.5) U33(14.5,1.5) U34(15.5,1.5) U35(16.5,1.5) U36(17.5,1.5) V1(-17.5,0.5) V2(-16.5,0.5) V3(-15.5,0.5) V4(-14.5,0.5) V5(-13.5,0.5) V6(-12.5,0.5) V7(-11.5,0.5) V8(-10.5,0.5) V9(-9.5,0.5) V10(-8.5,0.5) V11(-7.5,0.5) V12(-6.5,0.5) V13(-5.5,0.5) V14(-4.5,0.5) V15(-3.5,0.5) V16(-2.5,0.5) V17(-1.5,0.5) V18(-0.5,0.5) V19(0.5,0.5) V20(1.5,0.5) V21(2.5,0.5) V22(3.5,0.5) V23(4.5,0.5) V24(5.5,0.5) V25(6.5,0.5) V26(7.5,0.5) V27(8.5,0.5) V28(9.5,0.5) V29(10.5,0.5) V30(11.5,0.5) V31(12.5,0.5) V32(13.5,0.5) V33(14.5,0.5) V34(15.5,0.5) V35(16.5,0.5) V36(17.5,0.5) W1(-17.5,-0.5) W2(-16.5,-0.5) W3(-15.5,-0.5) W4(-14.5,-0.5) W5(-13.5,-0.5) W6(-12.5,-0.5) W7(-11.5,-0.5) W8(-10.5,-0.5) W9(-9.5,-0.5) W10(-8.5,-0.5) W11(-7.5,-0.5) W12(-6.5,-0.5) W13(-5.5,-0.5) W14(-4.5,-0.5) W15(-3.5,-0.5) W16(-2.5,-0.5) W17(-1.5,-0.5) W18(-0.5,-0.5) W19(0.5,-0.5) W20(1.5,-0.5) W21(2.5,-0.5) W22(3.5,-0.5) W23(4.5,-0.5) W24(5.5,-0.5) W25(6.5,-0.5) W26(7.5,-0.5) W27(8.5,-0.5) W28(9.5,-0.5) W29(10.5,-0.5) W30(11.5,-0.5) W31(12.5,-0.5) W32(13.5,-0.5) W33(14.5,-0.5) W34(15.5,-0.5) W35(16.5,-0.5) W36(17.5,-0.5) Y1(-17.5,-1.5) Y2(-16.5,-1.5) Y3(-15.5,-1.5) Y4(-14.5,-1.5) Y5(-13.5,-1.5) Y6(-12.5,-1.5) Y7(-11.5,-1.5) Y8(-10.5,-1.5) Y9(-9.5,-1.5) Y10(-8.5,-1.5) Y11(-7.5,-1.5) Y12(-6.5,-1.5) Y13(-5.5,-1.5) Y14(-4.5,-1.5) Y15(-3.5,-1.5) Y16(-2.5,-1.5) Y17(-1.5,-1.5) Y18(-0.5,-1.5) Y19(0.5,-1.5) Y20(1.5,-1.5) Y21(2.5,-1.5) Y22(3.5,-1.5) Y23(4.5,-1.5) Y24(5.5,-1.5) Y25(6.5,-1.5) Y26(7.5,-1.5) Y27(8.5,-1.5) Y28(9.5,-1.5) Y29(10.5,-1.5) Y30(11.5,-1.5) Y31(12.5,-1.5) Y32(13.5,-1.5) Y33(14.5,-1.5) Y34(15.5,-1.5) Y35(16.5,-1.5) Y36(17.5,-1.5)
Top Overlay:
  circle w0.25: c-19.4,17.5 r0.125
  region: -17.75,18.75 -18.75,17.75 -18.75,18.75
  lines w0.2: -18.75,17.75 -17.75,18.75 ; -18.75,-18.75 -18.75,18.75 18.75,18.75 18.75,-18.75 -18.75,-18.75
Mechanical 13:
  lines w0.1: -18.75,-18.75 -18.75,18.75 18.75,18.75 18.75,-18.75 -18.75,-18.75
Mechanical 15:
  lines w0.1: -0.5,0 0.5,0 ; 0,-0.5 0,0.5 ; -19.75,-19.75 -19.75,19.75 19.75,19.75 19.75,-19.75 -19.75,-19.75
3D body: height 0, standoff 0, extent -18.75,-18.75 18.75,18.75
